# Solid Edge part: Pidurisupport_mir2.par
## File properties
Author: Türk
Template: Iso Part.par
Last saved by: Türk
Revision: 2
Application: Solid Edge
Accuracy: 0,990
Username: Türk
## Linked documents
Pidurisupport.par
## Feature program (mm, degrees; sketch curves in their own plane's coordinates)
part copy "CopiedPart_1"
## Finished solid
Body 1: solid body, 64 faces, 125 edges, 62 vertices.
  Faces by surface: plane 27, cylinder 22, cone 13, spline 2
  Edges by curve: circle 63, line 40, intersection 10, ellipse 8, curve on surface 4
Bounding box of the edges (mm; curved faces can reach further): 96.748 x 152.000 x 85.456, from (-27.7472, -70, -26.5) to (69.0008, 82, 58.9555).
Cylindrical faces by radius (mm): R4 x8, R5 x2, R10 x6, R12.5 x3, R60 x2, R100 x1
Conical faces (half-angle, radius in mm at the cone's reference point): 45 deg R5 x2, 45 deg R12.5 x6, 45 deg R60 x1, 45 deg R61 x2, 45 deg R99 x1, 45 deg R100 x1
Planar faces by outward normal: +x 2, +y 8, -y 7, -z 2, oblique 8
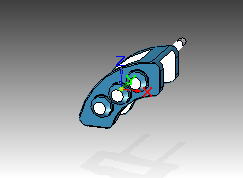
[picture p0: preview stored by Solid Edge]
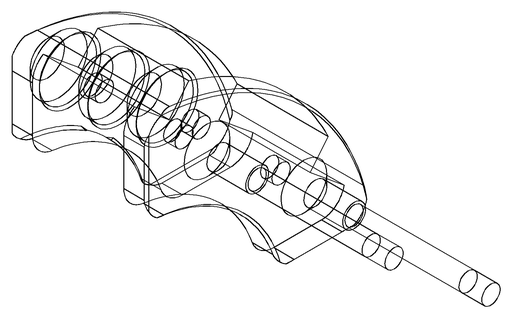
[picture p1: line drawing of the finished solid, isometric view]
